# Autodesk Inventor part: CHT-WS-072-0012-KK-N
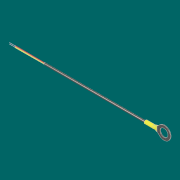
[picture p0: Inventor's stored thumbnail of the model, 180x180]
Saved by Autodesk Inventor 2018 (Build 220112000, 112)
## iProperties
Created: 2017-05
Part Number: CHT-WS-072-0012-KK-N
Material: Generic
Document SubType Name: Modeling
Designer: JN
Density: 1 g/cm^3
Appearance: Steel - Polished
Author: JN
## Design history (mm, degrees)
sketch "Sketch1"
  geometry: L1 (-6.161, 7.121)-(-10.033, 3.563); L2 (-10.033, 3.563)-(-10.033, -3.628); L3 (-10.033, -3.628)-(-6.161, -7.186); L4 (-10.033, -0.032)-(10.129, -0.032); L5 (4.711, 8.681)-(4.711, -8.745); C1 r 6.001 at (0.413, -0.032); A1 r 9.716 centre (0.413, -0.032) between (-6.161, -7.186) and (-6.161, 7.121)
  constraints: 10 end point, 5 point on circle, 2 centre point, 2 tangent, 2 vertical, 1 coincident, 1 midpoint, 1 other
  dimensions: "d0" = 12.0015 diameter of C1; "d1" = 19.431 diameter of A1; "d66" = 4.445 distance edge to line of C1 L2
extrude "Extrusion1" new body sketch "Sketch1" stored distance "d7" = 1.0668; taper "d8" = 0 deg
sketch "Sketch3"
  geometry: L1 (0, 0)-(-1.067, 0) reference; L2 (0, 7.191)-(0, 0) reference; L3 (0, 7.191)-(-1.067, 7.191) reference; L4 (-1.067, 0)-(-1.067, 7.191) reference; L5 (0.317, 7.508)-(-1.702, 7.508); L6 (-1.702, 7.508)-(-1.702, -0.318); L7 (-1.702, -0.318)-(0.317, -0.318); L8 (0.317, -0.318)-(0.317, 7.508); L9 (-0.692, 7.508)-(-0.692, -0.318); L10 (0.317, 3.595)-(-1.702, 3.595); 1 further point
  constraints: 12 end point, 6 parallel, 5 midpoint, 1 horizontal, 1 perpendicular
  dimensions: "d15" = 0.3175 distance between parallel lines of L2 L8; "d16" = 0.635 distance between parallel lines of L4 L6; "d17" = 0.3175 distance between parallel lines of L3 L5; "d18" = 0.3175 distance between parallel lines of L1 L7
  node "Projected Loop1"
workplane "Work Plane1"
sketch "Sketch4"
  geometry: L1 (0.317, -0.318)-(0.317, 7.508) reference; L2 (0.317, 7.508)-(-1.702, 7.508) reference; L3 (-1.702, 7.508)-(-1.702, -0.318) reference; L4 (-1.702, -0.318)-(0.317, -0.318) reference; L5 (0.317, 3.595)-(-1.702, 3.595); L6 (-0.692, 7.508)-(-0.692, -0.318); L7 (-2.337, 5.531)-(-2.337, 1.66); A1 r 2.54 centre (-0.692, 3.595) between (-2.337, 1.66) and (-2.337, 5.531); 2 further points
  constraints: 6 end point, 5 midpoint, 2 point on circle, 1 centre point, 1 coincident, 1 point on line, 1 vertical
  dimensions: "d37" = 5.08 diameter of A1; "d38" = 0.635 distance between parallel lines of L3 L7
sketch "3D Sketch1"
loft "Loft1" sketch "Sketch4", "3D Sketch1" dims "d21" = 0, "d22" = 90 deg, "d25" = 0, "d26" = 90 deg, "d39" = 0, "d40" = 90 deg
sketch "Sketch5"
  geometry: L1 (-1.645, 1.936)-(-1.645, -1.936) reference; A1 r 2.54 centre (0, 0) between (0.038, -2.54) and (0.843, 2.396) reference; A2 r 2.54 centre (0, 0) between (0.843, 2.396) and (-1.645, 1.936) reference; A3 r 2.54 centre (0, 0) between (0.843, 2.396) and (-1.645, 1.936) reference; A4 r 2.54 centre (0, 0) between (-1.645, -1.936) and (0.038, -2.54) reference; A5 r 2.54 centre (0, 0) between (0.038, -2.54) and (0.843, 2.396) reference
extrude "Extrusion3" new body sketch "Sketch5" distance "d27" = 12.7; taper "d28" = 0 deg
sketch "Sketch6" dims "d29" = 1.27, "d30" = 1.778
  geometry: L1 (0, 3.446)-(2.019, 3.446); L2 (2.54, 0)-(-1.645, 0); L3 (-1.645, 1.936)-(-1.645, -1.936) reference; A1 r 2.54 centre (0, 0) between (0.038, -2.54) and (0.843, 2.396) reference; 2 further points; 1 other entity
  constraints: 4 end point, 2 midpoint, 1 point on circle, 2 other
extrude "Extrusion4" cut sketch "Sketch6" stored distance "d32" = 12.7; taper "d33" = 0 deg
extrude "Extrusion5" new body sketch "Sketch6" distance "d34" = 152.4; taper "d35" = 0 deg
workplane "Work Plane2"
sketch "Sketch8"
  geometry: C1 r 0.635 at (0.187, 0.635) reference; C2 r 0.635 at (0.187, -0.635) reference; C3 r 0.635 at (0.187, 0.952); C4 r 0.635 at (0.187, -0.953)
  constraints: 2 centre point
  dimensions: "d43" = 1.27 diameter of C3; "d45" = 0.3175 distance of C1.centre C3.centre; "d46" = 1.27 diameter of C4; "d47" = 0.3175 distance of C2.centre C4.centre
sketch "3D Sketch2"
loft "Loft2" dims "d48" = 0, "d49" = 90 deg, "d50" = 0, "d51" = 90 deg, "d52" = 0, "d53" = 90 deg
loft "Loft3" dims "d54" = 0, "d55" = 90 deg, "d56" = 0, "d57" = 90 deg, "d58" = 0, "d59" = 90 deg
sketch "Sketch9"
  geometry: C1 r 0.381 at (0, 0)
  constraints: 1 centre point
  dimensions: "d60" = 0.762 diameter of C1
sketch "Sketch10"
  geometry: C1 r 0.381 at (0, 0)
  constraints: 1 centre point
  dimensions: "d61" = 0.762 diameter of C1
extrude "Extrusion6" join sketch "Sketch9" distance "d62" = 8.46667; taper "d63" = 0 deg
extrude "Extrusion7" join sketch "Sketch10" distance "d64" = 8.46667; taper "d65" = 0 deg
body "Solid1"
sketch "Sketch7"
  geometry: L1 (1.01, 1.395)-(1.01, -1.395) reference; L2 (-1.048, 0)-(1.492, 0); C1 r 0.635 at (0.187, 0.635); C2 r 0.635 at (0.187, -0.635); 3 further points; 3 other entities
  constraints: 4 end point, 2 centre point, 2 tangent, 2 vertical, 1 horizontal, 8 other
  dimensions: "d41" = 1.27 diameter of C1
body "Solid2"
body "Solid3"
body "Solid4"
node "Projected Loop5"
other parameters: "d3" = 14.986 (derived), "d5" = 10.49782 (derived), "d19" = 5.08, "d42" = 44.45
